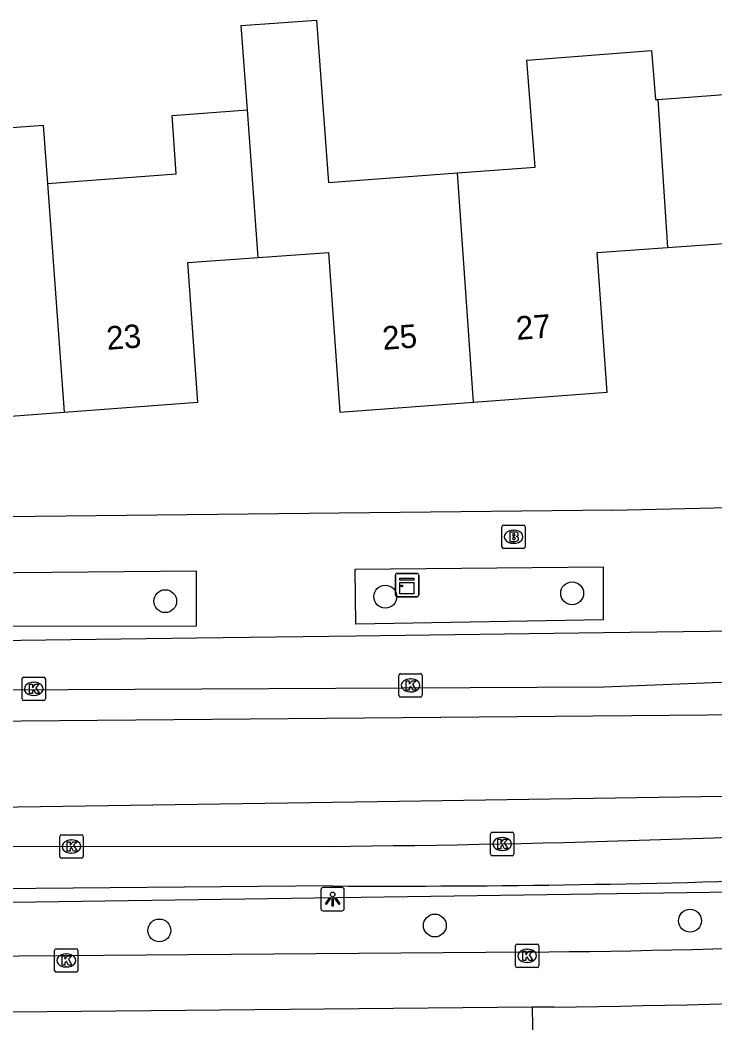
# Model space of a CAD drawing. Extents: x 163427 to 164190, y 380331 to 381641.
# Drawn here: x 163700.44 to 163730.15, y 380905.5 to 380948.41 of the extents above; entities that cross this region are included whole.
import ezdxf

# ---------------------------------------------------------------- set-up
doc = ezdxf.new("R2010")
doc.units = 0
for name, color, linetype in [('IMGEO_Boom', 7, 'Continuous'), ('IMGEO_Brandkraan', 7, 'Continuous'), ('IMGEO_Fietspad_gesloten', 7, 'Continuous'), ('IMGEO_Grasland_overig', 7, 'Continuous'), ('IMGEO_Kast', 7, 'Continuous'), ('IMGEO_Kolk', 7, 'Continuous'), ('IMGEO_Lichtpunt', 7, 'Continuous'), ('IMGEO_Pand', 7, 'Continuous'), ('IMGEO_Pand_nummerreeks', 7, 'Continuous'), ('IMGEO_Rijbaan_lokaal_gesloten', 7, 'Continuous'), ('IMGEO_Voetpad_open', 7, 'Continuous')]:
    doc.layers.add(name, color=color, linetype=linetype)

msp = doc.modelspace()

# ---------------------------------------------------------------- linework, layer by layer
at = {"layer": 'IMGEO_Boom'}
for centre in [(163716.055, 380923.736), (163724.043, 380923.881), (163706.648, 380923.544), (163729.08, 380909.871), (163706.396, 380909.455), (163718.173, 380909.667)]:
    msp.add_circle(centre, 0.489, dxfattribs=at)
at = {"layer": 'IMGEO_Brandkraan'}
for p, q in [((163721.038, 380925.873), (163721.038, 380926.725)), ((163721.113, 380926.799), (163721.965, 380926.799)), ((163722.039, 380926.725), (163722.039, 380925.873)), ((163721.526, 380926.579), (163721.551, 380926.579)), ((163721.965, 380925.799), (163721.113, 380925.799)), ((163721.549, 380926.019), (163721.524, 380926.019))]:
    msp.add_line(p, q, dxfattribs=at)
for points in [[(163721.038, 380925.873), (163721.038, 380926.725)], [(163721.113, 380926.799), (163721.965, 380926.799)], [(163722.039, 380926.725), (163722.039, 380925.873)], [(163721.386, 380926.499), (163721.386, 380926.099), (163721.599, 380926.099)], [(163721.617, 380926.499), (163721.386, 380926.499)], [(163721.565, 380926.418), (163721.511, 380926.418), (163721.511, 380926.342)], [(163721.511, 380926.342), (163721.564, 380926.342)], [(163721.573, 380926.266), (163721.511, 380926.266), (163721.511, 380926.185)], [(163721.965, 380925.799), (163721.113, 380925.799)], [(163721.511, 380926.185), (163721.573, 380926.185)]]:
    msp.add_lwpolyline(points, dxfattribs=at)
for centre, radius, start, end in [((163721.115, 380926.723), 0.0765, 91.552, 178.448), ((163721.115, 380926.723), 0.0765, 91.552, 178.448), ((163721.963, 380926.723), 0.0765, 1.552, 88.448), ((163721.963, 380926.723), 0.0765, 1.552, 88.448), ((163721.566, 380926.38), 0.0379, 267.8285, 90.9355), ((163721.574, 380926.225), 0.0404, 269.8759, 90.5077), ((163721.621, 380926.354), 0.145, 59.4692, 91.5367), ((163721.646, 380926.401), 0.0922, 285.5137, 58.1501), ((163721.651, 380926.209), 0.105, 301.3115, 78.989), ((163721.115, 380925.875), 0.0765, 181.552, 268.448), ((163721.115, 380925.875), 0.0765, 181.552, 268.448), ((163721.605, 380926.35), 0.251, 268.6676, 293.5347), ((163721.963, 380925.875), 0.0765, 271.552, 358.448), ((163721.963, 380925.875), 0.0765, 271.552, 358.448)]:
    msp.add_arc(centre, radius, start, end, dxfattribs=at)
for centre, major_axis, ratio, start_param, end_param in [((163721.525, 380926.299), (-0.387, 0.002), 0.722429, 4.712389, 7.853982), ((163721.55, 380926.299), (-0.39, 0.002), 0.717154, 1.570796, 4.712389)]:
    msp.add_ellipse(centre, major_axis=major_axis, ratio=ratio, start_param=start_param, end_param=end_param, dxfattribs=at)
at = {"layer": 'IMGEO_Fietspad_gesloten'}
msp.add_lwpolyline([(163682.067, 380913.066), (163713.656, 380913.052)], dxfattribs=at)
msp.add_arc((163708.45, 381513.774), 600.744, 270.49653, 276.074916, dxfattribs=at)
at = {"layer": 'IMGEO_Grasland_overig'}
msp.add_lwpolyline([(163722.338, 380906.17), (163722.383, 380903.697)], dxfattribs=at)
at = {"layer": 'IMGEO_Kast'}
for p, q in [((163716.487, 380923.808), (163716.487, 380924.649)), ((163716.487, 380924.649), (163716.487, 380923.808)), ((163716.562, 380924.733), (163717.403, 380924.733)), ((163717.403, 380924.733), (163716.562, 380924.733)), ((163717.487, 380924.658), (163717.487, 380923.817)), ((163717.487, 380923.817), (163717.487, 380924.658)), ((163717.412, 380923.733), (163716.571, 380923.733)), ((163716.571, 380923.733), (163717.412, 380923.733))]:
    msp.add_line(p, q, dxfattribs=at)
for points in [[(163716.682, 380924.523), (163717.282, 380924.523), (163717.282, 380924.438), (163716.682, 380924.438), (163716.682, 380924.523)], [(163716.682, 380924.348), (163717.282, 380924.348), (163717.282, 380923.859), (163716.682, 380923.859), (163716.682, 380924.348)]]:
    msp.add_lwpolyline(points, dxfattribs=at)
msp.add_circle((163716.766, 380924.197), 0.0377, dxfattribs=at)
for centre, start, end in [((163716.565, 380924.655), 92.4484, 184.2845), ((163716.565, 380924.655), 92.4484, 184.2845), ((163717.409, 380924.655), 2.4484, 94.2845), ((163717.409, 380924.655), 2.4484, 94.2845), ((163716.565, 380923.811), 182.4484, 274.2845), ((163716.565, 380923.811), 182.4484, 274.2845), ((163717.409, 380923.811), 272.4484, 4.2845), ((163717.409, 380923.811), 272.4484, 4.2845)]:
    msp.add_arc(centre, 0.0779, start, end, dxfattribs=at)
at = {"layer": 'IMGEO_Kolk'}
for p, q in [((163700.527, 380919.365), (163700.527, 380920.217)), ((163700.602, 380920.291), (163701.454, 380920.291)), ((163701.528, 380920.217), (163701.528, 380919.365)), ((163716.633, 380919.515), (163716.633, 380920.367)), ((163716.708, 380920.441), (163717.56, 380920.441)), ((163717.121, 380920.221), (163717.146, 380920.221)), ((163717.634, 380920.367), (163717.634, 380919.515)), ((163701.015, 380920.071), (163701.04, 380920.071)), ((163701.038, 380919.511), (163701.013, 380919.511)), ((163717.56, 380919.441), (163716.708, 380919.441)), ((163717.144, 380919.661), (163717.119, 380919.661)), ((163701.454, 380919.291), (163700.602, 380919.291)), ((163702.141, 380912.622), (163702.141, 380913.474)), ((163702.216, 380913.548), (163703.068, 380913.548)), ((163703.142, 380913.474), (163703.142, 380912.622)), ((163720.552, 380912.728), (163720.552, 380913.58)), ((163720.627, 380913.654), (163721.479, 380913.654)), ((163721.04, 380913.434), (163721.065, 380913.434)), ((163721.553, 380913.58), (163721.553, 380912.728)), ((163702.629, 380913.328), (163702.654, 380913.328)), ((163703.068, 380912.548), (163702.216, 380912.548)), ((163702.652, 380912.768), (163702.627, 380912.768)), ((163721.479, 380912.654), (163720.627, 380912.654)), ((163721.063, 380912.874), (163721.038, 380912.874)), ((163701.993, 380908.672), (163702.845, 380908.672)), ((163721.619, 380907.943), (163721.619, 380908.795)), ((163721.694, 380908.869), (163722.546, 380908.869)), ((163722.107, 380908.649), (163722.132, 380908.649)), ((163722.62, 380908.795), (163722.62, 380907.943)), ((163701.918, 380907.746), (163701.918, 380908.598)), ((163702.406, 380908.452), (163702.431, 380908.452)), ((163702.919, 380908.598), (163702.919, 380907.746)), ((163702.429, 380907.892), (163702.404, 380907.892)), ((163722.546, 380907.869), (163721.694, 380907.869)), ((163722.13, 380908.089), (163722.105, 380908.089)), ((163702.845, 380907.672), (163701.993, 380907.672))]:
    msp.add_line(p, q, dxfattribs=at)
for points in [[(163700.527, 380919.365), (163700.527, 380920.217)], [(163700.602, 380920.291), (163701.454, 380920.291)], [(163701.528, 380920.217), (163701.528, 380919.365)], [(163716.633, 380919.515), (163716.633, 380920.367)], [(163716.708, 380920.441), (163717.56, 380920.441)], [(163717.634, 380920.367), (163717.634, 380919.515)], [(163700.848, 380919.991), (163700.971, 380919.991), (163700.971, 380919.84), (163701.101, 380919.991), (163701.265, 380919.991), (163701.119, 380919.84), (163701.272, 380919.591), (163701.12, 380919.591), (163701.035, 380919.755), (163700.971, 380919.688), (163700.971, 380919.591), (163700.848, 380919.591), (163700.848, 380919.991)], [(163716.954, 380920.141), (163717.077, 380920.141), (163717.077, 380919.99), (163717.207, 380920.141), (163717.371, 380920.141), (163717.225, 380919.99), (163717.378, 380919.741), (163717.226, 380919.741), (163717.141, 380919.905), (163717.077, 380919.838), (163717.077, 380919.741), (163716.954, 380919.741), (163716.954, 380920.141)], [(163717.56, 380919.441), (163716.708, 380919.441)], [(163701.454, 380919.291), (163700.602, 380919.291)], [(163702.141, 380912.622), (163702.141, 380913.474)], [(163702.216, 380913.548), (163703.068, 380913.548)], [(163703.142, 380913.474), (163703.142, 380912.622)], [(163720.552, 380912.728), (163720.552, 380913.58)], [(163720.627, 380913.654), (163721.479, 380913.654)], [(163720.873, 380913.354), (163720.996, 380913.354), (163720.996, 380913.203), (163721.126, 380913.354), (163721.29, 380913.354), (163721.144, 380913.203), (163721.297, 380912.954), (163721.145, 380912.954), (163721.06, 380913.118), (163720.996, 380913.051), (163720.996, 380912.954), (163720.873, 380912.954), (163720.873, 380913.354)], [(163721.553, 380913.58), (163721.553, 380912.728)], [(163702.462, 380913.248), (163702.585, 380913.248), (163702.585, 380913.097), (163702.715, 380913.248), (163702.879, 380913.248), (163702.733, 380913.097), (163702.886, 380912.848), (163702.734, 380912.848), (163702.649, 380913.012), (163702.585, 380912.945), (163702.585, 380912.848), (163702.462, 380912.848), (163702.462, 380913.248)], [(163703.068, 380912.548), (163702.216, 380912.548)], [(163721.479, 380912.654), (163720.627, 380912.654)], [(163701.993, 380908.672), (163702.845, 380908.672)], [(163721.619, 380907.943), (163721.619, 380908.795)], [(163721.694, 380908.869), (163722.546, 380908.869)], [(163722.62, 380908.795), (163722.62, 380907.943)], [(163701.918, 380907.746), (163701.918, 380908.598)], [(163702.239, 380908.372), (163702.362, 380908.372), (163702.362, 380908.221), (163702.492, 380908.372), (163702.656, 380908.372), (163702.51, 380908.221), (163702.663, 380907.972), (163702.511, 380907.972), (163702.426, 380908.136), (163702.362, 380908.069), (163702.362, 380907.972), (163702.239, 380907.972), (163702.239, 380908.372)], [(163702.919, 380908.598), (163702.919, 380907.746)], [(163721.94, 380908.569), (163722.063, 380908.569), (163722.063, 380908.418), (163722.193, 380908.569), (163722.357, 380908.569), (163722.211, 380908.418), (163722.364, 380908.169), (163722.212, 380908.169), (163722.127, 380908.333), (163722.063, 380908.266), (163722.063, 380908.169), (163721.94, 380908.169), (163721.94, 380908.569)], [(163722.546, 380907.869), (163721.694, 380907.869)], [(163702.845, 380907.672), (163701.993, 380907.672)]]:
    msp.add_lwpolyline(points, dxfattribs=at)
for centre, start, end in [((163700.604, 380920.215), 91.552, 178.448), ((163700.604, 380920.215), 91.552, 178.448), ((163701.452, 380920.215), 1.552, 88.448), ((163701.452, 380920.215), 1.552, 88.448), ((163716.71, 380920.365), 91.552, 178.448), ((163716.71, 380920.365), 91.552, 178.448), ((163717.558, 380920.365), 1.552, 88.448), ((163717.558, 380920.365), 1.552, 88.448), ((163700.604, 380919.367), 181.552, 268.448), ((163700.604, 380919.367), 181.552, 268.448), ((163701.452, 380919.367), 271.552, 358.448), ((163701.452, 380919.367), 271.552, 358.448), ((163716.71, 380919.517), 181.552, 268.448), ((163716.71, 380919.517), 181.552, 268.448), ((163717.558, 380919.517), 271.552, 358.448), ((163717.558, 380919.517), 271.552, 358.448), ((163702.218, 380913.472), 91.552, 178.448), ((163702.218, 380913.472), 91.552, 178.448), ((163703.066, 380913.472), 1.552, 88.448), ((163703.066, 380913.472), 1.552, 88.448), ((163720.629, 380913.578), 91.552, 178.448), ((163720.629, 380913.578), 91.552, 178.448), ((163721.477, 380913.578), 1.552, 88.448), ((163721.477, 380913.578), 1.552, 88.448), ((163702.218, 380912.624), 181.552, 268.448), ((163702.218, 380912.624), 181.552, 268.448), ((163703.066, 380912.624), 271.552, 358.448), ((163703.066, 380912.624), 271.552, 358.448), ((163720.629, 380912.73), 181.552, 268.448), ((163720.629, 380912.73), 181.552, 268.448), ((163721.477, 380912.73), 271.552, 358.448), ((163721.477, 380912.73), 271.552, 358.448), ((163701.995, 380908.596), 91.552, 178.448), ((163701.995, 380908.596), 91.552, 178.448), ((163702.843, 380908.596), 1.552, 88.448), ((163702.843, 380908.596), 1.552, 88.448), ((163721.696, 380908.793), 91.552, 178.448), ((163721.696, 380908.793), 91.552, 178.448), ((163722.544, 380908.793), 1.552, 88.448), ((163722.544, 380908.793), 1.552, 88.448), ((163721.696, 380907.945), 181.552, 268.448), ((163721.696, 380907.945), 181.552, 268.448), ((163722.544, 380907.945), 271.552, 358.448), ((163722.544, 380907.945), 271.552, 358.448), ((163701.995, 380907.748), 181.552, 268.448), ((163701.995, 380907.748), 181.552, 268.448), ((163702.843, 380907.748), 271.552, 358.448), ((163702.843, 380907.748), 271.552, 358.448)]:
    msp.add_arc(centre, 0.0765, start, end, dxfattribs=at)
for centre, major_axis, ratio, start_param, end_param in [((163717.12, 380919.941), (-0.387, 0.002), 0.722429, 4.712389, 7.853982), ((163717.145, 380919.941), (-0.39, 0.002), 0.717154, 1.570796, 4.712389), ((163701.014, 380919.791), (-0.387, 0.002), 0.722429, 4.712389, 7.853982), ((163701.039, 380919.791), (-0.39, 0.002), 0.717154, 1.570796, 4.712389), ((163702.628, 380913.048), (-0.387, 0.002), 0.722429, 4.712389, 7.853982), ((163721.039, 380913.154), (-0.387, 0.002), 0.722429, 4.712389, 7.853982), ((163721.064, 380913.154), (-0.39, 0.002), 0.717154, 1.570796, 4.712389), ((163702.653, 380913.048), (-0.39, 0.002), 0.717154, 1.570796, 4.712389), ((163722.106, 380908.369), (-0.387, 0.002), 0.722429, 4.712389, 7.853982), ((163722.131, 380908.369), (-0.39, 0.002), 0.717154, 1.570796, 4.712389), ((163702.405, 380908.172), (-0.387, 0.002), 0.722429, 4.712389, 7.853982), ((163702.43, 380908.172), (-0.39, 0.002), 0.717154, 1.570796, 4.712389)]:
    msp.add_ellipse(centre, major_axis=major_axis, ratio=ratio, start_param=start_param, end_param=end_param, dxfattribs=at)
at = {"layer": 'IMGEO_Lichtpunt'}
for p, q in [((163713.307, 380911.198), (163713.307, 380910.391)), ((163713.307, 380911.198), (163713.307, 380910.391)), ((163714.209, 380911.293), (163713.401, 380911.293)), ((163714.209, 380911.293), (163713.401, 380911.293)), ((163714.303, 380910.391), (163714.303, 380911.198)), ((163714.303, 380910.391), (163714.303, 380911.198)), ((163713.401, 380910.297), (163714.209, 380910.297)), ((163713.401, 380910.297), (163714.209, 380910.297))]:
    msp.add_line(p, q, dxfattribs=at)
for points in [[(163713.681, 380910.862), (163713.72, 380910.834), (163713.532, 380910.572), (163713.494, 380910.599), (163713.681, 380910.862)], [(163713.783, 380910.814), (163713.83, 380910.814), (163713.83, 380910.492), (163713.783, 380910.492), (163713.783, 380910.814)], [(163713.893, 380910.834), (163713.931, 380910.861), (163714.118, 380910.599), (163714.079, 380910.571), (163713.893, 380910.834)]]:
    msp.add_lwpolyline(points, dxfattribs=at)
msp.add_circle((163713.806, 380910.996), 0.0994, dxfattribs=at)
for centre, start, end in [((163713.401, 380911.198), 90, 180), ((163713.401, 380911.198), 90, 180), ((163714.209, 380911.198), 0, 90), ((163714.209, 380911.198), 0, 90), ((163713.401, 380910.391), 180, 270), ((163713.401, 380910.391), 180, 270), ((163714.209, 380910.391), 270, 0), ((163714.209, 380910.391), 270, 360)]:
    msp.add_arc(centre, 0.0946, start, end, dxfattribs=at)
at = {"layer": 'IMGEO_Pand'}
for points in [[(163710.161, 380944.564), (163709.895, 380948.167), (163713.108, 380948.405), (163713.623, 380941.458), (163719.147, 380941.867)], [(163719.147, 380941.867), (163722.465, 380942.113), (163722.108, 380946.684), (163727.44, 380947.102), (163727.604, 380945.003), (163727.704, 380945.01)], [(163727.704, 380945.01), (163730.915, 380945.248), (163731.164, 380941.884), (163736.674, 380942.292)], [(163727.704, 380945.01), (163728.115, 380938.671)], [(163701.611, 380941.411), (163707.123, 380941.82), (163706.938, 380944.325), (163710.161, 380944.564)], [(163710.623, 380938.249), (163710.161, 380944.564)], [(163689.392, 380943.015), (163694.379, 380943.385), (163698.175, 380943.666), (163701.426, 380943.907), (163701.611, 380941.411)], [(163719.833, 380932.053), (163719.147, 380941.867)], [(163701.611, 380941.411), (163702.327, 380931.626)], [(163719.833, 380932.053), (163725.545, 380932.479), (163725.113, 380938.454), (163728.115, 380938.671)], [(163728.115, 380938.671), (163731.127, 380938.889), (163731.541, 380933.174), (163731.622, 380932.049), (163737.335, 380932.476)], [(163702.327, 380931.626), (163708.037, 380932.054), (163707.612, 380938.035), (163710.623, 380938.249)], [(163710.623, 380938.249), (163713.633, 380938.463), (163714.119, 380931.626), (163719.833, 380932.053)], [(163687.297, 380934.382), (163693.454, 380934.853), (163693.296, 380936.957), (163696.168, 380937.172), (163696.325, 380935.073), (163696.614, 380931.197), (163702.327, 380931.626)]]:
    msp.add_lwpolyline(points, dxfattribs=at)
at = {"layer": 'IMGEO_Rijbaan_lokaal_gesloten'}
for points in [[(163868.839, 380925.415), (163864.416, 380926.273), (163861.674, 380926.755), (163860.332, 380926.988), (163857.627, 380927.192), (163854.666, 380927.243), (163850.072, 380927.013), (163838.639, 380925.686), (163814.648, 380922.928), (163796.579, 380920.681), (163765.443, 380917.107), (163748.701, 380915.881), (163736.043, 380915.269), (163715.728, 380914.962), (163682.084, 380914.454)], [(163681.983, 380918.123), (163693.971, 380918.37), (163736.348, 380918.742), (163760.51, 380920.229), (163795.266, 380924.289), (163797.781, 380924.606), (163797.614, 380926.005)], [(163753.097, 380921.245), (163745.157, 380920.677), (163735.429, 380920.259), (163725.418, 380919.865), (163682.402, 380919.644)]]:
    msp.add_lwpolyline(points, dxfattribs=at)
at = {"layer": 'IMGEO_Voetpad_open'}
for points in [[(163725.783, 380927.438), (163685.488, 380926.999)], [(163714.769, 380924.908), (163725.363, 380925.013), (163725.365, 380922.748), (163714.793, 380922.558), (163714.769, 380924.908)], [(163697.165, 380924.74), (163707.974, 380924.834), (163707.975, 380922.469), (163697.21, 380922.455), (163697.165, 380924.74)], [(163697.239, 380921.831), (163707.981, 380921.97), (163714.799, 380922.059), (163725.388, 380922.196), (163732.228, 380922.285), (163735.065, 380922.322), (163742.839, 380922.615)], [(163682.195, 380910.411), (163739.877, 380911.235), (163746.499, 380911.581), (163752.866, 380911.981), (163755.984, 380912.162), (163755.162, 380909.924), (163750.228, 380909.548)], [(163713.816, 380911.358), (163685.239, 380911.109)], [(163722.166, 380908.53), (163682.232, 380908.211), (163682.195, 380910.411)], [(163722.338, 380906.17), (163682.307, 380905.781), (163677.393, 380905.733), (163675.415, 380905.712)], [(163723.266, 380906.179), (163722.338, 380906.17)]]:
    msp.add_lwpolyline(points, dxfattribs=at)
for centre, radius, start, end in [((163713.545, 381571.458), 644.136, 271.088632, 272.843824), ((163716.103, 381431.457), 520.104, 269.74804, 274.39591), ((163716.512, 381450.296), 544.159, 270.7112, 277.113), ((163717.505, 381424.3), 515.791, 270.51777, 273.63742)]:
    msp.add_arc(centre, radius, start, end, dxfattribs=at)

# ---------------------------------------------------------------- texts
at = {"layer": 'IMGEO_Pand_nummerreeks'}
for s, rotation, p in [('27', 4.2695, (163721.677, 380934.718)), ('23', 4.2905, (163704.168, 380934.292)), ('25', 4.2695, (163715.964, 380934.291))]:
    msp.add_text(s, height=1, rotation=rotation, dxfattribs=at).set_placement(p)

doc.saveas('drawing.dxf')
